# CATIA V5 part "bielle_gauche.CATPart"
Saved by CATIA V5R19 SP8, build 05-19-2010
Part number: bielle_gauche
Bounding box of the stored display mesh (mm): x -900 to -825, y -929.893 to -300.464, z 80.253 to 289.943
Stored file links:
  G:\EU_thinkMotion\CFAO_2010\MMS_groupe2\MMS_groupe2\OK\mmartini\mmartiniCFAO\bielle_gauche.CATPart
  C:\Users\Mathieu Martini\Desktop\CFAO\Animation\CFAO.CATProduct
  G:\EU_thinkMotion\CFAO_2010\MMS_groupe2\MMS_groupe2\OK\mmartini\mmartiniCFAO\Squelette.CATPart
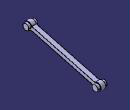
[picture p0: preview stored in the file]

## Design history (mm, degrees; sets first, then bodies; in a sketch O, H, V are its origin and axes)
External parameters (linked from other documents)
  External.diametre_canon = 150 mm
  External.diametre_verin = 120 mm
AxisSystem1: origin (0, 0, 0), X (1, 0, 0), Y (0, 1, 0), Z (0, 0, 1)
Set1
  Sketch1 on Plane1, origin (-825, 0, 0), H (0, 1, 0), V (0, 0, 1)
    construction line L1 (-283.75, 89.4819) -> (-396.4551, 139.5731)
    reference projected point E1 (-376.0481, 130.5033) from Point1
    reference projected line E2 through (-74.2268, -167.0103) direction (0.9138, -0.4061) from Line1
    arc A1 centre (-330.3575, 110.1964) radius 30 from (-359.2989, 102.2974) to (-351.669, 131.3109) ccw
    point P3 (-330.3575, 110.1964)
    reference projected point E3 (-376.0481, 130.5033) from Point1
    circle A2 centre (-330.3575, 110.1964) radius 24
    point P4 (-330.3575, 110.1964)
    construction line L2 (-900, 124.6269) -> (-900, 293.1039)
    reference projected point E4 (-900, 150) from Point2
    arc A3 centre (-900, 260) radius 30 from (-871.0586, 267.8991) to (-878.6885, 238.8855) ccw
    point P7 (-900, 260)
    reference projected point E5 (-900, 150) from Point2
    circle A4 centre (-900, 260) radius 24
    axis line L3 (-900, 260) -> (-330.3575, 110.1964)
    point P8 (-357.7719, 122.3806)
    line L4 (-351.669, 131.3109) -> (-871.0586, 267.8991)
    point P9 (-351.669, 131.3109)
    point P10 (-871.0586, 267.8991)
    point P11 (-878.6885, 238.8855)
    point P12 (-359.2989, 102.2974)
    line L5 (-359.2989, 102.2974) -> (-878.6885, 238.8855)
    distance P3 E3 = 50 {= External.diametre_canon /3}
    radius A1 = 30 {= External.diametre_verin /4}
    radius A2 = 24 {= External.diametre_verin /5}
    distance P7 E5 = 110 {= External.diametre_canon *0.7333333333}
    radius A3 = 30 {= External.diametre_verin /4}
    radius A4 = 24 {= External.diametre_verin /5}
    distance L4 L3 = 15 {= External.diametre_canon /10}
    radius A2 = 24 {= External.diametre_verin /5} (reference)
    coincidence: L1 E1, P3 L1, P4 L1, L2 E4, P7 L2, P8 A1, P8 L1, P4 P3
    parallelism: L1 E2
    vertical: L2 V
    symmetry: P10 P11 L3, P9 P12 L3, L4 L5 L3
Set2
  Plane1 "Plan_jambe_gauche_roue": linked copy from another document
  Point1: linked copy from another document
  Line1: linked copy from another document
  Point2: linked copy from another document
Body1 (main body)
  Pad1: profile Sketch1, direction (-1, 0, 0), length 57.1429 {= External.diametre_verin /2.1}
  Sketch2 on start face of Pad1, origin (-825, 0, 0), H (0, 1, 0), V (0, 0, 1)
    projected arc E1 centre (-330.3575, 110.1964) radius 30 from (-359.2989, 102.2974) to (-351.669, 131.3109) ccw from edge [face of Pad1 from Sketch1.A1 | start face of Pad1]
    projected line E2 (-351.669, 131.3109) -> (-871.0586, 267.8991) from edge [face of Pad1 from Sketch1.L4 | start face of Pad1]
    projected arc E3 centre (-900, 260) radius 30 from (-871.0586, 267.8991) to (-878.6885, 238.8855) ccw from edge [face of Pad1 from Sketch1.A3 | start face of Pad1]
    projected line E4 (-878.6885, 238.8855) -> (-359.2989, 102.2974) from edge [face of Pad1 from Sketch1.L5 | start face of Pad1]
  Pocket1: profile Sketch2, direction (-1, 0, 0), length 20 {= External.diametre_verin /6}
  Sketch3 on Plane1, origin (-825, 0, 0), H (0, 1, 0), V (0, 0, 1)
    projected circle E1 centre (-900, 260) radius 24 from edge [face of Pad1 from Sketch1.A4 | end face of Pad1]
    projected circle E2 centre (-330.3575, 110.1964) radius 24 from edge [face of Pad1 from Sketch1.A2 | end face of Pad1]
  Pad2: profile Sketch3, direction (-1, 0, 0), length 75 {= External.diametre_canon /2}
